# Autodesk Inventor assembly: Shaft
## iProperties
Created: 2007-11
Part Number: Shaft
Document SubType Name: Assembly
Designer: CM
Mass: 718.372 g
Surface Area: 157.281 cm^2
Volume: 91.5124 cm^3
Density: 7.85 g/cm^3
ClientObjectVersion: 1
Author: CM
